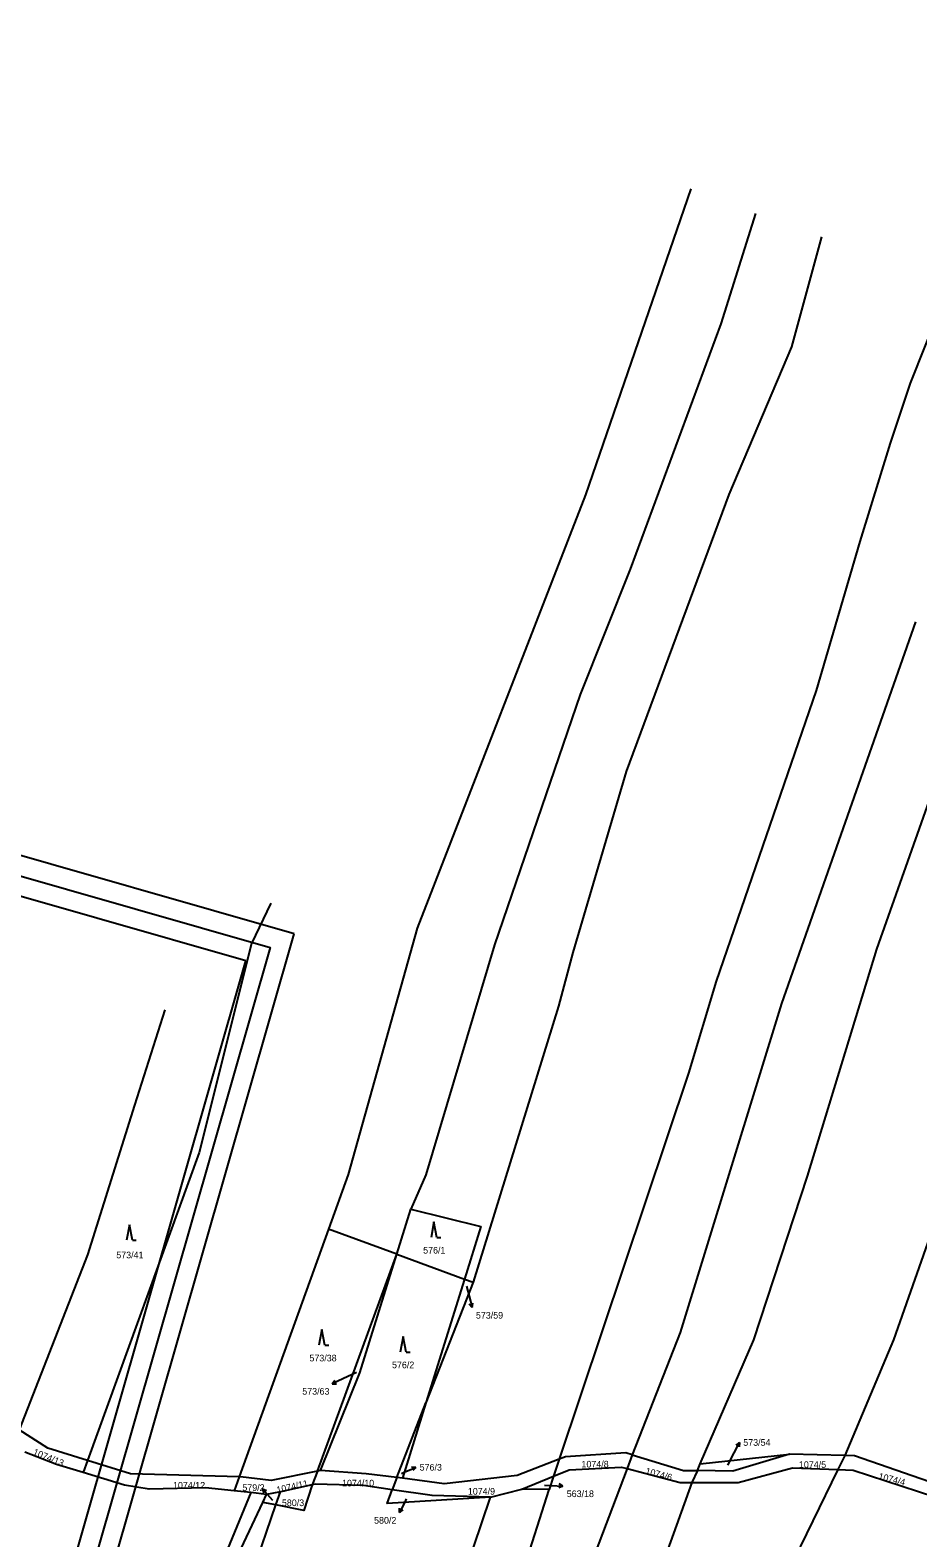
# Model space of a CAD drawing. Extents: x -738085 to -734306, y -1122197 to -1119753.
# Drawn here: x -736794 to -736566.9, y -1121585.1 to -1121199.1 of the extents above; entities that cross this region are included whole.
import ezdxf

# ---------------------------------------------------------------- set-up
doc = ezdxf.new("R2010")
doc.units = 0
for name, color, linetype in [('Hranice parcel', 7, 'Continuous'), ('Parcelní čísla', 7, 'Continuous'), ('Pop  PČ popisy', 7, 'Continuous'), ('Vrstva 1', 7, 'Continuous'), ('Značky kultur', 7, 'Continuous')]:
    doc.layers.add(name, color=color, linetype=linetype)

msp = doc.modelspace()

# ---------------------------------------------------------------- linework, layer by layer
at = {"layer": 'Hranice parcel'}
for p, q in [((-736700.18, -1121512.45), (-736696.59, -1121500.9)), ((-736717.64, -1121506.04), (-736740.51, -1121569.45)), ((-736700.18, -1121512.45), (-736717.64, -1121506.04)), ((-736720.5, -1121567.97), (-736700.18, -1121512.45)), ((-736700.18, -1121512.45), (-736682.85, -1121518.8)), ((-736682.85, -1121518.8), (-736692.73, -1121550.53)), ((-736680.69, -1121519.59), (-736692.73, -1121550.53)), ((-736682.85, -1121518.8), (-736680.69, -1121519.59)), ((-736700.16, -1121569.64), (-736692.73, -1121550.53)), ((-736692.73, -1121550.53), (-736698.73, -1121569.82)), ((-736779.28, -1121565.27), (-736780.39, -1121568.35)), ((-736658.64, -1121564.93), (-736660.08, -1121569.24)), ((-736639.98, -1121563.82), (-736641.3, -1121567.31)), ((-736623.31, -1121567.84), (-736622.55, -1121566.09)), ((-736622.55, -1121566.09), (-736599.77, -1121563.65)), ((-736585.59, -1121563.97), (-736599.77, -1121563.65)), ((-736585.59, -1121563.97), (-736587.35, -1121567.59)), ((-736740.51, -1121569.45), (-736741.79, -1121573.01)), ((-736720.5, -1121567.97), (-736721.8, -1121571.52)), ((-736719.71, -1121567.81), (-736720.5, -1121567.97)), ((-736700.16, -1121569.64), (-736701.37, -1121572.75)), ((-736698.73, -1121569.82), (-736700.16, -1121569.64)), ((-736668.17, -1121572.56), (-736660.08, -1121569.24)), ((-736660.08, -1121569.24), (-736661.23, -1121572.67)), ((-736641.3, -1121567.31), (-736654.1, -1121601.1)), ((-736623.31, -1121567.84), (-736624.69, -1121570.89)), ((-736587.35, -1121567.59), (-736609.89, -1121613.75)), ((-736737.5, -1121573.48), (-736741.79, -1121573.01)), ((-736733.51, -1121573.96), (-736737.5, -1121573.48)), ((-736734.46, -1121575.99), (-736733.51, -1121573.96)), ((-736729.98, -1121573.3), (-736733.51, -1121573.96)), ((-736731.13, -1121576.64), (-736729.98, -1121573.3)), ((-736721.8, -1121571.52), (-736729.98, -1121573.3)), ((-736676.26, -1121574.62), (-736668.17, -1121572.56)), ((-736671.39, -1121604.72), (-736661.23, -1121572.67)), ((-736661.23, -1121572.67), (-736668.17, -1121572.56)), ((-736744.38, -1121615.25), (-736731.13, -1121576.64)), ((-736731.13, -1121576.64), (-736734.46, -1121575.99)), ((-736684.73, -1121599.8), (-736676.26, -1121574.62))]:
    msp.add_line(p, q, dxfattribs=at)
for points in [[(-736624.99, -1121239.72), (-736651.96, -1121318.03), (-736694.99, -1121429), (-736712.61, -1121492.08), (-736717.64, -1121506.04)], [(-736608.44, -1121246.09), (-736617.32, -1121274.31), (-736640.46, -1121337.13), (-736653.3, -1121369.18), (-736675.18, -1121433.26), (-736692.78, -1121492.11), (-736696.59, -1121500.9)], [(-736591.59, -1121252.06), (-736599.2, -1121280.22), (-736615.22, -1121317.97), (-736641.54, -1121388.87), (-736655.17, -1121435.19), (-736658.81, -1121448.99), (-736680.69, -1121519.59)], [(-736560.99, -1121269.75), (-736568.85, -1121289.52), (-736574.01, -1121304.82), (-736581.74, -1121330.01), (-736592.9, -1121368.18), (-736618.5, -1121442.55), (-736625.55, -1121466.1), (-736658.64, -1121564.93)], [(-736486.66, -1121271.03), (-736491.67, -1121290.25), (-736499.08, -1121316.84), (-736539.39, -1121438.32), (-736573.13, -1121534.37), (-736585.59, -1121563.97)], [(-736567.47, -1121350.56), (-736601.81, -1121448.28), (-736627.73, -1121532.52), (-736639.98, -1121563.82)], [(-736622.55, -1121566.09), (-736608.84, -1121534.41), (-736595.15, -1121492.44), (-736577.4, -1121434.36), (-736549.64, -1121355.71)], [(-736732.44, -1121422.58), (-736737.33, -1121432.88), (-736750.77, -1121486.44), (-736779.28, -1121565.27)], [(-736759.54, -1121449.86), (-736767.29, -1121474.26), (-736779.34, -1121512.65), (-736796.78, -1121557.37)], [(-736696.59, -1121500.9), (-736678.68, -1121505.38), (-736682.85, -1121518.8)], [(-736719.71, -1121567.81), (-736709.64, -1121542.84), (-736700.18, -1121512.45)], [(-736779.28, -1121565.27), (-736789.46, -1121562.09), (-736796.78, -1121557.37)], [(-736780.39, -1121568.35), (-736787.24, -1121566.27), (-736795.38, -1121563.11)], [(-736740.51, -1121569.45), (-736768.31, -1121568.69), (-736779.28, -1121565.27)], [(-736658.64, -1121564.93), (-736669.42, -1121569.11), (-736688.09, -1121571.22), (-736698.73, -1121569.82)], [(-736639.98, -1121563.82), (-736641.57, -1121563.34), (-736657.03, -1121564.31), (-736658.64, -1121564.93)], [(-736639.98, -1121563.82), (-736626.89, -1121567.78), (-736623.31, -1121567.84)], [(-736599.77, -1121563.65), (-736614.21, -1121568.02), (-736623.31, -1121567.84)], [(-736561.99, -1121571.42), (-736583.07, -1121564.03), (-736585.59, -1121563.97)], [(-736741.79, -1121573.01), (-736749.12, -1121572.22), (-736763.51, -1121572.56), (-736769.85, -1121571.55), (-736780.39, -1121568.35)], [(-736720.5, -1121567.97), (-736732.3, -1121570.41), (-736740.15, -1121569.46), (-736740.51, -1121569.45)], [(-736700.16, -1121569.64), (-736708.05, -1121568.64), (-736719.71, -1121567.81)], [(-736660.08, -1121569.24), (-736656.14, -1121567.62), (-736642.74, -1121566.93), (-736641.3, -1121567.31)], [(-736641.3, -1121567.31), (-736627.7, -1121570.9), (-736624.69, -1121570.89)], [(-736624.69, -1121570.89), (-736612.9, -1121570.87), (-736599, -1121567.1), (-736587.35, -1121567.59)], [(-736587.35, -1121567.59), (-736583.41, -1121567.75), (-736562.59, -1121574.56), (-736556.62, -1121574.94)], [(-736737.5, -1121573.48), (-736748.87, -1121600.98), (-736761.91, -1121618.36)], [(-736721.8, -1121571.52), (-736723.99, -1121578.04), (-736731.13, -1121576.64)], [(-736701.37, -1121572.75), (-736708.74, -1121571.67), (-736721.07, -1121571.36), (-736721.8, -1121571.52)], [(-736676.26, -1121574.62), (-736702.65, -1121576.26), (-736701.37, -1121572.75)], [(-736676.26, -1121574.62), (-736691.11, -1121574.25), (-736701.37, -1121572.75)], [(-736624.69, -1121570.89), (-736629.45, -1121583.94), (-736636.93, -1121604.74)], [(-736757.76, -1121619.52), (-736750.29, -1121609.72), (-736734.46, -1121575.99)]]:
    msp.add_lwpolyline(points, dxfattribs=at)
at = {"layer": 'Pop  PČ popisy'}
for p, q in [((-736682.37, -1121520.66), (-736681.71, -1121523.21)), ((-736681.71, -1121523.21), (-736680.93, -1121526.11)), ((-736680.93, -1121526.11), (-736681.68, -1121525.27)), ((-736680.93, -1121526.11), (-736680.71, -1121525.01)), ((-736710.53, -1121542.73), (-736714.03, -1121544.33)), ((-736714.03, -1121544.33), (-736716.75, -1121545.6)), ((-736716.75, -1121545.6), (-736716.05, -1121544.72)), ((-736716.75, -1121545.6), (-736715.63, -1121545.63)), ((-736613.92, -1121563.31), (-736612.56, -1121560.64)), ((-736612.56, -1121560.64), (-736613.46, -1121561.3)), ((-736612.56, -1121560.64), (-736612.57, -1121561.76)), ((-736615.54, -1121566.48), (-736613.92, -1121563.31)), ((-736698.98, -1121568.56), (-736698.11, -1121568.18)), ((-736698.11, -1121568.18), (-736695.35, -1121567.01)), ((-736695.35, -1121567.01), (-736696.46, -1121566.94)), ((-736695.35, -1121567.01), (-736696.07, -1121567.86)), ((-736732.58, -1121574.75), (-736734.55, -1121572.49)), ((-736734.55, -1121572.49), (-736733.51, -1121572.91)), ((-736734.55, -1121572.49), (-736734.27, -1121573.57)), ((-736662.39, -1121571.54), (-736660.72, -1121571.63)), ((-736660.72, -1121571.63), (-736657.72, -1121571.79)), ((-736657.72, -1121571.79), (-736658.75, -1121572.24)), ((-736657.72, -1121571.79), (-736658.7, -1121571.24)), ((-736731.93, -1121575.49), (-736732.58, -1121574.75)), ((-736699.47, -1121578.6), (-736699.48, -1121577.48)), ((-736698.15, -1121575.9), (-736699.47, -1121578.6)), ((-736699.47, -1121578.6), (-736698.58, -1121577.92)), ((-736697.77, -1121575.11), (-736698.15, -1121575.9))]:
    msp.add_line(p, q, dxfattribs=at)
at = {"layer": 'Vrstva 1'}
for points in [[(-736726.43, -1121430.48), (-737533.93, -1121199.12), (-737615.73, -1121484.62), (-736808.23, -1121715.98)], [(-737530.5, -1121205.3), (-736732.61, -1121433.9), (-736811.65, -1121709.79), (-737609.54, -1121481.19)], [(-736738.79, -1121437.33), (-737330, -1121267.94), (-737406.29, -1121534.23), (-736815.08, -1121703.62)]]:
    msp.add_lwpolyline(points, close=True, dxfattribs=at)
at = {"layer": 'Značky kultur'}
for p, q in [((-736690.68, -1121504.2), (-736691.43, -1121508.2)), ((-736689.93, -1121508.2), (-736690.68, -1121504.2)), ((-736768.59, -1121504.9), (-736769.34, -1121508.9)), ((-736767.84, -1121508.9), (-736768.59, -1121504.9)), ((-736689.93, -1121508.2), (-736688.93, -1121508.2)), ((-736767.84, -1121508.9), (-736766.84, -1121508.9)), ((-736719.36, -1121531.72), (-736720.11, -1121535.72)), ((-736718.61, -1121535.72), (-736719.36, -1121531.72)), ((-736698.55, -1121533.5), (-736699.3, -1121537.5)), ((-736697.8, -1121537.5), (-736698.55, -1121533.5)), ((-736718.61, -1121535.72), (-736717.61, -1121535.72)), ((-736697.8, -1121537.5), (-736696.8, -1121537.5))]:
    msp.add_line(p, q, dxfattribs=at)

# ---------------------------------------------------------------- texts
at = {"layer": 'Parcelní čísla'}
for s, p in [('573/41', (-736771.95, -1121513.5)), ('576/1', (-736693.45, -1121512.29)), ('573/59', (-736679.95, -1121528.94)), ('573/38', (-736722.54, -1121539.89)), ('576/2', (-736701.41, -1121541.64)), ('573/63', (-736724.37, -1121548.41)), ('573/54', (-736611.56, -1121561.49)), ('576/3', (-736694.35, -1121567.85)), ('1074/8', (-736652.95, -1121567.05)), ('1074/5', (-736597.32, -1121567.15)), ('1074/10', (-736714.2, -1121571.9)), ('1074/12', (-736757.44, -1121572.45)), ('579/2', (-736739.7, -1121573.04)), ('1074/9', (-736682.02, -1121574)), ('563/18', (-736656.72, -1121574.63)), ('580/3', (-736729.58, -1121576.94)), ('580/2', (-736706, -1121581.43))]:
    msp.add_text(s, height=1.7, dxfattribs=at).set_placement(p)
for s, rotation, p in [('1074/13', 338, (-736793.41, -1121563.74)), ('1074/11', 13, (-736730.74, -1121573.69)), ('1074/6', 345, (-736636.73, -1121568.69)), ('1074/4', 346, (-736577.11, -1121570.03))]:
    msp.add_text(s, height=1.7, rotation=rotation, dxfattribs=at).set_placement(p)

doc.saveas('drawing.dxf')
